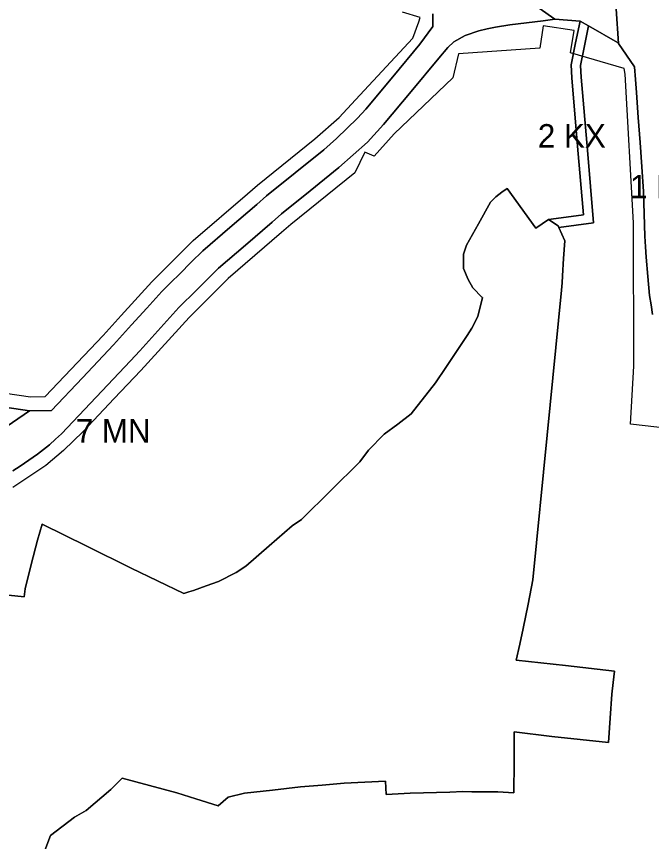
# Model space of a CAD drawing. Extents: x 7423432 to 7425824, y 5537848 to 5539677.
# Drawn here: x 7424018.1 to 7424289.1, y 5538420.5 to 5538772.8 of the extents above; entities that cross this region are included whole.
import ezdxf

# ---------------------------------------------------------------- set-up
doc = ezdxf.new("R2010")
doc.units = 0
for name, color, linetype in [('linie_rozgraniczajace', 7, 'Continuous'), ('linie_zabudowy_nieprzekraczalne', 7, 'Continuous'), ('oznaczenia_przeznaczen', 7, 'Continuous')]:
    doc.layers.add(name, color=color, linetype=linetype)

msp = doc.modelspace()

# ---------------------------------------------------------------- linework, layer by layer
at = {"layer": 'linie_rozgraniczajace'}
for points in [[(7424235.92, 5538780.12), (7424247.87, 5538771.6), (7424242.88, 5538770.92), (7424235.78, 5538770.03), (7424228.66, 5538769.13), (7424222.53, 5538768.22), (7424218.97, 5538767.45), (7424215.4, 5538766.69), (7424209.65, 5538764.69), (7424204.74, 5538761.95), (7424202.18, 5538759.53), (7424198.3, 5538754.92), (7424186.52, 5538740.77), (7424174.75, 5538726.63), (7424167.91, 5538719.04), (7424161.81, 5538713.63), (7424155.7, 5538708.23), (7424143.47, 5538698.37), (7424131.23, 5538688.5), (7424127.24, 5538684.99), (7424115.79, 5538675.17), (7424104.34, 5538665.35), (7424099.61, 5538660.61), (7424094.88, 5538655.87), (7424087.36, 5538648.43), (7424080.94, 5538641.37), (7424070.63, 5538630.03), (7424066.72, 5538625.74)], [(7424273.98, 5538776.07), (7424275.09, 5538761.16), (7424274.55, 5538761.67), (7424262.3, 5538768.72), (7424258.64, 5538770.83), (7424253.26, 5538771.21), (7424247.87, 5538771.6), (7424235.92, 5538780.12)], [(7424289.56, 5538645.57), (7424288.93, 5538649.59), (7424288.29, 5538653.61), (7424287.58, 5538661.77), (7424286.87, 5538669.93), (7424286.6, 5538674.45), (7424286.34, 5538678.98), (7424286.05, 5538688.49), (7424285.76, 5538698), (7424285.04, 5538708.5), (7424284.31, 5538718.99), (7424283.49, 5538729.65), (7424282.66, 5538740.31), (7424282.26, 5538745.8), (7424281.86, 5538751.29), (7424275.09, 5538761.16), (7424273.98, 5538776.07)], [(7424195.78, 5538773.91), (7424195.8, 5538768.54), (7424190.27, 5538760.9), (7424178.75, 5538747.06), (7424167.23, 5538733.23), (7424163.58, 5538729.28), (7424154.59, 5538720.6), (7424149.25, 5538715.87), (7424137.01, 5538706.01), (7424124.79, 5538696.15), (7424120.63, 5538692.49), (7424109.08, 5538682.59), (7424097.54, 5538672.69), (7424092.67, 5538667.81), (7424087.8, 5538662.94), (7424083.97, 5538659.14), (7424080.14, 5538655.35), (7424073.63, 5538648.2), (7424067.13, 5538641.05), (7424063.26, 5538636.79), (7424059.39, 5538632.53), (7424046.17, 5538618.53), (7424032.96, 5538604.53), (7424023.61, 5538604.33), (7423993.67, 5538608.75)], [(7424011.34, 5538596.04), (7424023.61, 5538604.33), (7424032.96, 5538604.53), (7424046.17, 5538618.53), (7424059.39, 5538632.53), (7424063.26, 5538636.79), (7424067.13, 5538641.05), (7424073.63, 5538648.2), (7424080.14, 5538655.35), (7424083.97, 5538659.14), (7424087.8, 5538662.94), (7424092.67, 5538667.81), (7424097.54, 5538672.69), (7424109.08, 5538682.59), (7424120.63, 5538692.49), (7424124.79, 5538696.15), (7424137.01, 5538706.01), (7424149.25, 5538715.87), (7424154.59, 5538720.6), (7424163.58, 5538729.28), (7424167.23, 5538733.23), (7424178.75, 5538747.06), (7424190.27, 5538760.9), (7424195.8, 5538768.54), (7424195.78, 5538773.91)], [(7424016.5, 5538578.81), (7424019.55, 5538580.78), (7424023.27, 5538583.3), (7424026.98, 5538585.81), (7424029.53, 5538587.86), (7424032.08, 5538589.91), (7424034.68, 5538592.23), (7424037.28, 5538594.55), (7424052, 5538610.14), (7424066.72, 5538625.74), (7424070.63, 5538630.03), (7424080.94, 5538641.37), (7424087.36, 5538648.43), (7424094.88, 5538655.87), (7424099.61, 5538660.61), (7424104.34, 5538665.35), (7424115.79, 5538675.17), (7424127.24, 5538684.99), (7424131.23, 5538688.5), (7424143.47, 5538698.37), (7424155.7, 5538708.23), (7424161.81, 5538713.63), (7424167.91, 5538719.04), (7424174.75, 5538726.63), (7424186.52, 5538740.77), (7424198.3, 5538754.92), (7424202.18, 5538759.53), (7424204.74, 5538761.95), (7424209.65, 5538764.69), (7424215.4, 5538766.69), (7424218.97, 5538767.45), (7424222.53, 5538768.22), (7424228.66, 5538769.13), (7424235.78, 5538770.03), (7424242.88, 5538770.92), (7424247.87, 5538771.6), (7424253.26, 5538771.21), (7424258.64, 5538770.83), (7424256.75, 5538761.48), (7424254.86, 5538752.14), (7424255.09, 5538746.58), (7424257.58, 5538717.32), (7424260.08, 5538688.07), (7424252.65, 5538687.1), (7424245.23, 5538686.14), (7424239.8, 5538682.34), (7424227.52, 5538699.31), (7424225.26, 5538697.71), (7424222.73, 5538695.72), (7424220.34, 5538693.45), (7424215.27, 5538684.25), (7424210.2, 5538675.05), (7424208.82, 5538671.25), (7424208.81, 5538665.13), (7424210.82, 5538660.52), (7424212.92, 5538656.94), (7424216.79, 5538652.81), (7424217.01, 5538652.73), (7424215.03, 5538644.65), (7424212.45, 5538639.67), (7424210.44, 5538636.6), (7424208.43, 5538633.53), (7424201.37, 5538622.92), (7424196.85, 5538616.34), (7424186.52, 5538603.1), (7424180.78, 5538598.72), (7424175.03, 5538594.34), (7424168.38, 5538587.51), (7424164.63, 5538582.65), (7424152.27, 5538570.36), (7424139.91, 5538558.08), (7424139.75, 5538557.96), (7424135.77, 5538555.24), (7424125.86, 5538546.68), (7424115.94, 5538538.11)], [(7424021.79, 5538394.37), (7424032.63, 5538423.01), (7424042.87, 5538430.85), (7424047.74, 5538433.71), (7424058.36, 5538442.73), (7424063.14, 5538447.51), (7424086.47, 5538441.21), (7424094.6, 5538438.67), (7424104.11, 5538435.71), (7424108.44, 5538439.45), (7424115.45, 5538441.09), (7424127.36, 5538442.44), (7424139.27, 5538443.8), (7424148.57, 5538444.59), (7424157.87, 5538445.38), (7424166.69, 5538445.84), (7424175.51, 5538446.3), (7424175.83, 5538440.54), (7424180.99, 5538440.83), (7424186.14, 5538441.12), (7424191.77, 5538441.28), (7424197.4, 5538441.44), (7424203.03, 5538441.6), (7424208.66, 5538441.76), (7424212.39, 5538441.73), (7424219.85, 5538441.67), (7424223.58, 5538441.64), (7424230.36, 5538441.24), (7424230.46, 5538454.3), (7424230.57, 5538467.37), (7424246.52, 5538465.33), (7424258.64, 5538464.03), (7424270.76, 5538462.73), (7424271.49, 5538473.09), (7424272.23, 5538483.44), (7424272.79, 5538488.34), (7424273.35, 5538493.24), (7424252.37, 5538495.57), (7424231.38, 5538497.89), (7424232.89, 5538504.68), (7424234.39, 5538511.47), (7424236.41, 5538521.83), (7424238.43, 5538532.19), (7424244.59, 5538594.04), (7424250.74, 5538655.9), (7424250.94, 5538658.98), (7424251.13, 5538662.06), (7424251.6, 5538669.49), (7424252.07, 5538676.91), (7424249.63, 5538682.68), (7424257.01, 5538683.64), (7424264.39, 5538684.6), (7424261.74, 5538715.71), (7424259.09, 5538746.83), (7424258.88, 5538751.82), (7424260.59, 5538760.27), (7424262.3, 5538768.72), (7424274.55, 5538761.67), (7424275.09, 5538761.16), (7424281.86, 5538751.29), (7424282.26, 5538745.8), (7424282.66, 5538740.31), (7424283.49, 5538729.65), (7424284.31, 5538718.99), (7424285.04, 5538708.5), (7424285.76, 5538698), (7424286.05, 5538688.49), (7424286.34, 5538678.98), (7424286.6, 5538674.45), (7424286.87, 5538669.93), (7424287.58, 5538661.77), (7424288.29, 5538653.61), (7424288.93, 5538649.59), (7424289.56, 5538645.57)], [(7424009.11, 5538526.28), (7424021.37, 5538524.88), (7424021.77, 5538528.38), (7424024.38, 5538538.78), (7424026.99, 5538549.18), (7424029.05, 5538555.93), (7424048.05, 5538546.56), (7424067.06, 5538537.19), (7424078.27, 5538531.79), (7424089.48, 5538526.39), (7424091.57, 5538527.05), (7424093.66, 5538527.71), (7424098.99, 5538529.62), (7424104.32, 5538531.53), (7424111.82, 5538535.36), (7424115.94, 5538538.11), (7424125.86, 5538546.68), (7424135.77, 5538555.24), (7424139.75, 5538557.96), (7424139.91, 5538558.08), (7424152.27, 5538570.36), (7424164.63, 5538582.65), (7424168.38, 5538587.51), (7424175.03, 5538594.34), (7424180.78, 5538598.72), (7424186.52, 5538603.1), (7424196.85, 5538616.34), (7424201.37, 5538622.92), (7424208.43, 5538633.53), (7424210.44, 5538636.6), (7424212.45, 5538639.67), (7424215.03, 5538644.65), (7424217.01, 5538652.73), (7424216.79, 5538652.81), (7424212.92, 5538656.94), (7424210.82, 5538660.52), (7424208.81, 5538665.13), (7424208.82, 5538671.25), (7424210.2, 5538675.05), (7424215.27, 5538684.25), (7424220.34, 5538693.45), (7424222.73, 5538695.72), (7424225.26, 5538697.71), (7424227.52, 5538699.31), (7424239.8, 5538682.34), (7424245.23, 5538686.14), (7424249.35, 5538683.34), (7424249.63, 5538682.68), (7424252.07, 5538676.91)], [(7424252.07, 5538676.91), (7424251.6, 5538669.49), (7424251.13, 5538662.06), (7424250.94, 5538658.98), (7424250.74, 5538655.9), (7424244.59, 5538594.04), (7424238.43, 5538532.19), (7424236.41, 5538521.83), (7424234.39, 5538511.47), (7424232.89, 5538504.68), (7424231.38, 5538497.89), (7424252.37, 5538495.57), (7424273.35, 5538493.24), (7424272.79, 5538488.34), (7424272.23, 5538483.44), (7424271.49, 5538473.09), (7424270.76, 5538462.73), (7424258.64, 5538464.03), (7424246.52, 5538465.33), (7424230.57, 5538467.37), (7424230.46, 5538454.3), (7424230.36, 5538441.24), (7424223.58, 5538441.64), (7424219.85, 5538441.67), (7424212.39, 5538441.73), (7424208.66, 5538441.76), (7424203.03, 5538441.6), (7424197.4, 5538441.44), (7424191.77, 5538441.28), (7424186.14, 5538441.12), (7424180.99, 5538440.83), (7424175.83, 5538440.54), (7424175.51, 5538446.3), (7424166.69, 5538445.84), (7424157.87, 5538445.38), (7424148.57, 5538444.59), (7424139.27, 5538443.8), (7424127.36, 5538442.44), (7424115.45, 5538441.09), (7424108.44, 5538439.45), (7424104.11, 5538435.71), (7424094.6, 5538438.67), (7424086.47, 5538441.21), (7424063.14, 5538447.51), (7424058.36, 5538442.73), (7424047.74, 5538433.71), (7424042.87, 5538430.85), (7424032.63, 5538423.01), (7424021.79, 5538394.37)], [(7424066.72, 5538625.74), (7424052, 5538610.14), (7424037.28, 5538594.55), (7424034.68, 5538592.23), (7424032.08, 5538589.91), (7424029.53, 5538587.86), (7424026.98, 5538585.81), (7424023.27, 5538583.3), (7424019.55, 5538580.78), (7424016.5, 5538578.81)], [(7423993.67, 5538608.75), (7424023.61, 5538604.33), (7424011.34, 5538596.04)], [(7424115.94, 5538538.11), (7424111.82, 5538535.36), (7424104.32, 5538531.53), (7424098.99, 5538529.62), (7424093.66, 5538527.71), (7424091.57, 5538527.05), (7424089.48, 5538526.39), (7424078.27, 5538531.79), (7424067.06, 5538537.19), (7424048.05, 5538546.56), (7424029.05, 5538555.93), (7424026.99, 5538549.18), (7424024.38, 5538538.78), (7424021.77, 5538528.38), (7424021.37, 5538524.88), (7424009.11, 5538526.28)]]:
    msp.add_lwpolyline(points, dxfattribs=at)
msp.add_lwpolyline([(7424245.23, 5538686.14), (7424252.65, 5538687.1), (7424260.08, 5538688.07), (7424257.58, 5538717.32), (7424255.09, 5538746.58), (7424254.86, 5538752.14), (7424256.75, 5538761.48), (7424258.64, 5538770.83), (7424262.3, 5538768.72), (7424260.59, 5538760.27), (7424258.88, 5538751.82), (7424259.09, 5538746.83), (7424261.74, 5538715.71), (7424264.39, 5538684.6), (7424257.01, 5538683.64), (7424249.63, 5538682.68), (7424249.35, 5538683.34)], close=True, dxfattribs=at)
at = {"layer": 'linie_zabudowy_nieprzekraczalne'}
for points in [[(7423964.71, 5538619.08), (7424023.99, 5538610.34), (7424030.32, 5538610.47), (7424054.99, 5538636.61), (7424062.7, 5538645.09), (7424075.8, 5538659.5), (7424083.57, 5538667.19), (7424093.45, 5538677.09), (7424116.69, 5538697.02), (7424120.92, 5538700.74), (7424145.37, 5538720.45), (7424155.73, 5538729.63), (7424162.72, 5538737.19), (7424187.19, 5538763.46), (7424189.8, 5538770.48), (7424190.32, 5538772.33), (7424182.83, 5538774.63)], [(7424296.44, 5538596.88), (7424280.14, 5538598.69), (7424281.56, 5538623.4), (7424281.43, 5538684.7), (7424281.43, 5538684.7), (7424281.43, 5538684.7), (7424281.43, 5538684.7), (7424281.43, 5538684.7), (7424277.9, 5538748.13), (7424277.9, 5538748.13), (7424277.9, 5538748.13), (7424277.9, 5538748.13), (7424277.9, 5538748.13), (7424277.44, 5538750.62), (7424254.6, 5538757.23), (7424256.09, 5538766.79), (7424242.92, 5538768.76), (7424241.51, 5538759.17), (7424206.79, 5538756.76), (7424204.38, 5538746.6), (7424179.28, 5538722.7), (7424170.69, 5538713.09), (7424166.81, 5538714.77), (7424162.42, 5538705.94)], [(7424162.42, 5538705.94), (7424135.1, 5538683.92), (7424131.18, 5538680.46), (7424108.42, 5538660.95), (7424099.12, 5538651.62), (7424091.69, 5538644.27), (7424071.13, 5538621.66), (7424059.72, 5538609.58), (7424046.46, 5538595.53), (7424038.18, 5538587.44), (7424030.59, 5538581.01), (7424016.53, 5538571.67)]]:
    msp.add_lwpolyline(points, dxfattribs=at)

# ---------------------------------------------------------------- texts
at = {"layer": 'oznaczenia_przeznaczen'}
for s, p in [('2 KX', (7424240.61, 5538716.8)), ('1 KDZ', (7424279.95, 5538695.11)), ('7 MN', (7424043.33, 5538590.84))]:
    msp.add_text(s, height=10, dxfattribs=at).set_placement(p)

doc.saveas('drawing.dxf')
